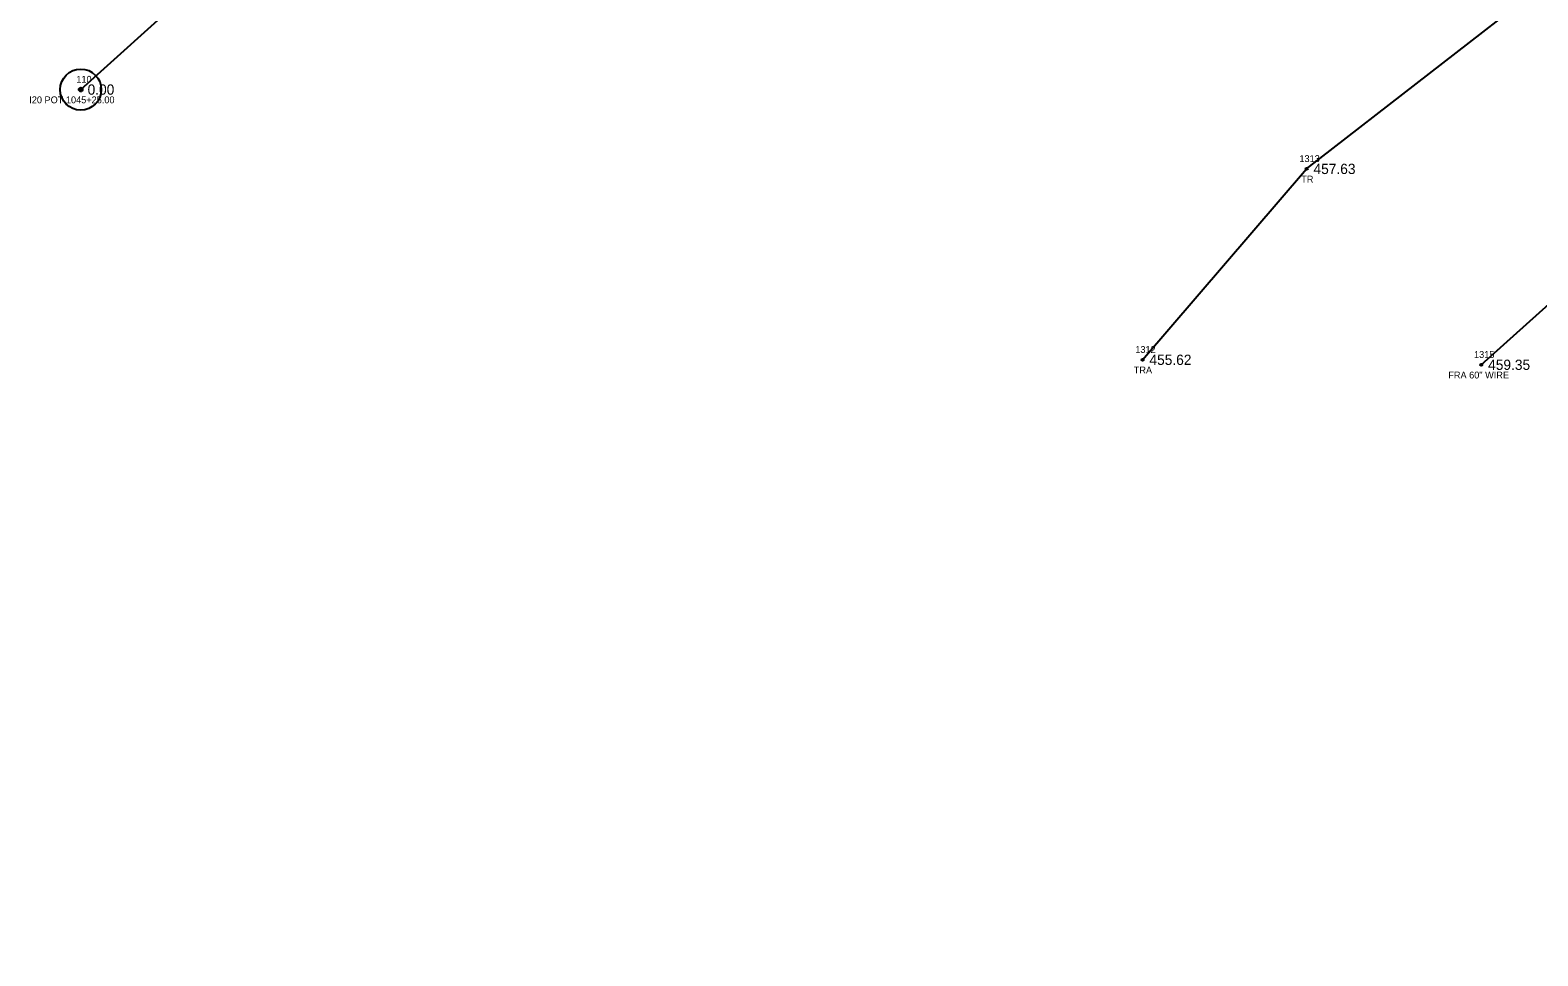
# Model space of a CAD drawing. Extents: x 1745838 to 1751419, y 649211 to 655806.
# Drawn here: x 1749016.3 to 1749236.5, y 651116.3 to 651251.5 of the extents above; entities that cross this region are included whole.
import ezdxf

# ---------------------------------------------------------------- set-up
doc = ezdxf.new("R2010")
doc.units = 0
for name, color, linetype in [('RD_EX_Fence_Other', 7, 'Continuous'), ('RD_EX_Fence_Other_txCode', 7, 'Continuous'), ('RD_EX_TX_Fence_Other_ELEV', 7, 'Continuous'), ('RD_EX_TX_VEG_ELEV', 7, 'Continuous'), ('RD_EX_VEG', 7, 'Continuous'), ('RD_EX_VEG_txCode', 7, 'Continuous'), ('RD_HC_Cl', 7, 'Continuous'), ('RD_HC_Data', 7, 'Continuous'), ('RD_HC_Survey_ELEV', 7, 'Continuous'), ('RD_HC_txCode', 7, 'Continuous'), ('RD_SMD_Locator', 7, 'Continuous')]:
    doc.layers.add(name, color=color, linetype=linetype)

msp = doc.modelspace()

# ---------------------------------------------------------------- linework, layer by layer
at = {"layer": 'RD_EX_Fence_Other'}
msp.add_lwpolyline([(1749228.24, 651202.64), (1749249.97, 651222.14), (1749249.97, 651222.14), (1749291.03, 651176.48), (1749358.68, 651100.15), (1749424.34, 651025.98), (1749461.84, 650986.11), (1749495.25, 650947.39), (1749527.17, 650911.79), (1749559.6, 650874.95), (1749594.11, 650836.92), (1749630.2, 650798.28), (1749673.95, 650750.13)], dxfattribs=at)
at = {"layer": 'RD_EX_VEG'}
msp.add_lwpolyline([(1749178.77, 651203.37), (1749202.73, 651231.24), (1749238.66, 651259.14), (1749294.64, 651175.67), (1749358.68, 651100.15), (1749424.34, 651025.98), (1749461.84, 650986.11), (1749495.25, 650947.39), (1749527.17, 650911.79), (1749559.6, 650874.95), (1749594.11, 650836.92), (1749630.2, 650798.28), (1749696.62, 650725.69)], dxfattribs=at)
at = {"layer": 'RD_HC_Cl'}
msp.add_line((1749023.67, 651242.82), (1749320.94, 651510.46), dxfattribs=at)
at = {"layer": 'RD_HC_Data'}
for radius in [3, 0.282]:
    msp.add_circle((1749023.67, 651242.82), radius, dxfattribs=at)
at = {"layer": 'RD_SMD_Locator'}
for centre in [(1749023.67, 651242.82), (1749202.73, 651231.24), (1749178.77, 651203.37), (1749228.24, 651202.64)]:
    msp.add_circle(centre, 0.15, dxfattribs=at)

# ---------------------------------------------------------------- texts
at = {"layer": 'RD_EX_Fence_Other_txCode'}
for s, p in [('1315', (1749227.18, 651203.64)), ('FRA 60" WIRE', (1749223.42, 651200.64))]:
    msp.add_text(s, height=1, dxfattribs=at).set_placement(p)
at = {"layer": 'RD_EX_TX_Fence_Other_ELEV'}
msp.add_text('459.35', height=1.5, dxfattribs=at).set_placement((1749229.24, 651201.89))
at = {"layer": 'RD_EX_TX_VEG_ELEV'}
for s, p in [('457.63', (1749203.73, 651230.49)), ('455.62', (1749179.77, 651202.62))]:
    msp.add_text(s, height=1.5, dxfattribs=at).set_placement(p)
at = {"layer": 'RD_EX_VEG_txCode'}
for s, p in [('1313', (1749201.67, 651232.24)), ('TR', (1749201.94, 651229.24)), ('1312', (1749177.7, 651204.37)), ('TRA', (1749177.48, 651201.37))]:
    msp.add_text(s, height=1, dxfattribs=at).set_placement(p)
at = {"layer": 'RD_HC_Survey_ELEV'}
msp.add_text('0.00', height=1.5, dxfattribs=at).set_placement((1749024.67, 651242.07))
at = {"layer": 'RD_HC_txCode'}
for s, p in [('110', (1749023.02, 651243.82)), ('I20 POT 1045+25.00', (1749016.15, 651240.82))]:
    msp.add_text(s, height=1, dxfattribs=at).set_placement(p)

doc.saveas('drawing.dxf')
